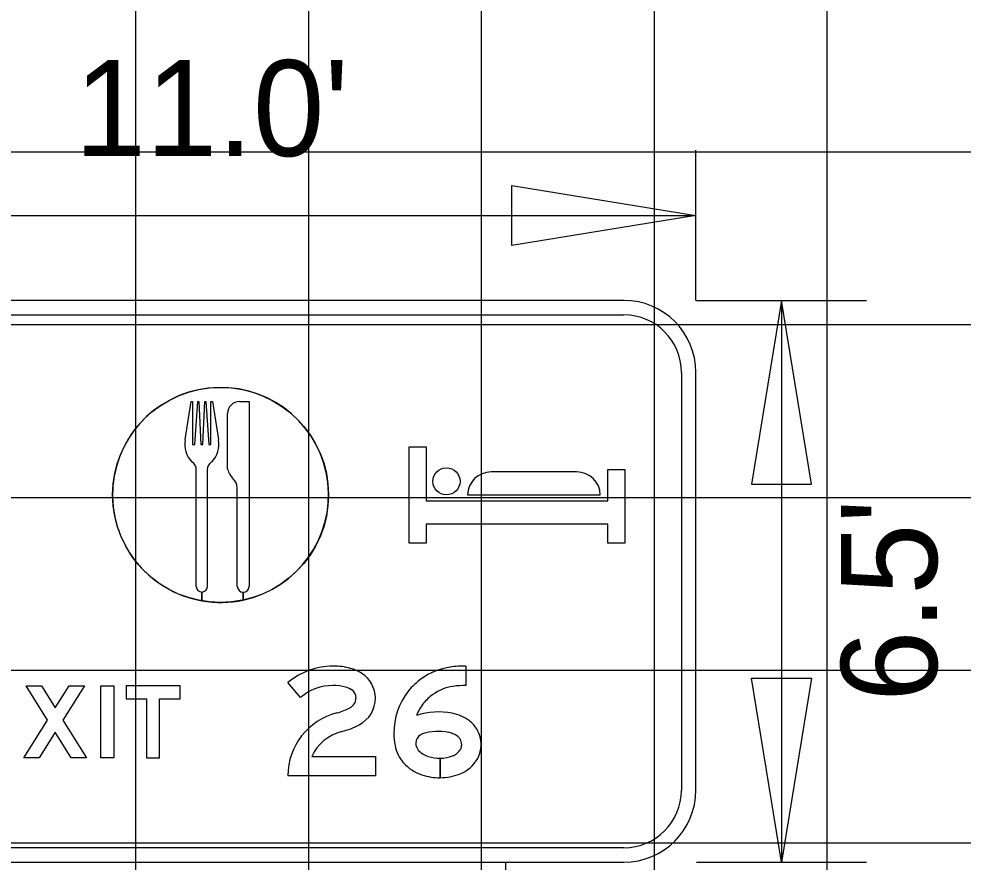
# Model space of a CAD drawing. Extents: x 1797809 to 2198143, y 249608 to 1237864.
# Drawn here: x 2194983.51 to 2194994.43, y 1237299.88 to 1237309.65 of the extents above; entities that cross this region are included whole.
import ezdxf

# ---------------------------------------------------------------- set-up
doc = ezdxf.new("R2010")
doc.units = 0
for name, color, linetype in [('GSBWFILL', 7, 'Continuous'), ('GSCOLORFILL', 7, 'Continuous'), ('GSDIMS', 7, 'Continuous'), ('GSOUTLINE', 7, 'Continuous'), ('GSSHT', 7, 'Continuous'), ('Level 55', 7, 'Continuous')]:
    doc.layers.add(name, color=color, linetype=linetype)

msp = doc.modelspace()

# ---------------------------------------------------------------- linework, layer by layer
at = {"layer": 'GSBWFILL'}
for points in [[(2194985.429, 1237304.774), (2194985.5, 1237305.214), (2194985.516, 1237305.214), (2194985.516, 1237304.716), (2194985.543, 1237304.716), (2194985.577, 1237305.214), (2194985.588, 1237305.214), (2194985.61, 1237304.716), (2194985.635, 1237304.716), (2194985.657, 1237305.214), (2194985.668, 1237305.214), (2194985.703, 1237304.716), (2194985.729, 1237304.716), (2194985.729, 1237305.214), (2194985.745, 1237305.214)], [(2194985.745, 1237305.214), (2194985.816, 1237304.774)], [(2194986.059, 1237305.214), (2194986.172, 1237305.214), (2194986.172, 1237303.078)], [(2194985.921, 1237304.433), (2194985.921, 1237305.077)], [(2194985.559, 1237303.073), (2194985.559, 1237304.424)], [(2194985.686, 1237304.424), (2194985.686, 1237303.073)], [(2194989.96, 1237304.401), (2194988.972, 1237304.401)], [(2194986.033, 1237303.078), (2194986.033, 1237304.216)], [(2194988.698, 1237304.134), (2194990.234, 1237304.134)], [(2194985.622, 1237302.909), (2194985.622, 1237303.009)], [(2194985.623, 1237303.009), (2194985.623, 1237302.909)], [(2194986.103, 1237302.917), (2194986.103, 1237303.009)], [(2194986.103, 1237303.009), (2194986.103, 1237302.917)], [(2194988.679, 1237302.153), (2194988.679, 1237301.928)], [(2194986.765, 1237301.79), (2194986.62, 1237301.962)], [(2194986.894, 1237301.107), (2194987.631, 1237301.107), (2194987.631, 1237300.882), (2194986.62, 1237300.882)], [(2194988.382, 1237301.085), (2194988.382, 1237300.861)], [(2194988.382, 1237300.861), (2194988.382, 1237301.085)]]:
    msp.add_lwpolyline(points, dxfattribs=at)
for points in [[(2194990.32, 1237303.794), (2194988.22, 1237303.794), (2194988.22, 1237303.576), (2194988.021, 1237303.576), (2194988.021, 1237304.692), (2194988.22, 1237304.692), (2194988.22, 1237304.065), (2194990.32, 1237304.065), (2194990.32, 1237304.427), (2194990.519, 1237304.427), (2194990.519, 1237303.576), (2194990.32, 1237303.576)], [(2194984.112, 1237301.09), (2194983.926, 1237301.386), (2194983.741, 1237301.09), (2194983.564, 1237301.09), (2194983.838, 1237301.527), (2194983.589, 1237301.923), (2194983.766, 1237301.923), (2194983.926, 1237301.668), (2194984.087, 1237301.923), (2194984.264, 1237301.923), (2194984.015, 1237301.527), (2194984.288, 1237301.09)], [(2194984.455, 1237301.09), (2194984.455, 1237301.923), (2194984.605, 1237301.923), (2194984.605, 1237301.09)], [(2194984.746, 1237301.773), (2194984.984, 1237301.773), (2194984.984, 1237301.09), (2194985.133, 1237301.09), (2194985.133, 1237301.773), (2194985.371, 1237301.773), (2194985.371, 1237301.923), (2194984.746, 1237301.923)]]:
    msp.add_lwpolyline(points, close=True, dxfattribs=at)
for centre, major_axis, ratio, start_param, end_param in [((2194985.84, 1237304.134), (1.249, 0), 0.996678, 4.924399, 10.820496), ((2194986.059, 1237305.077), (0.138, 0), 0.996678, 1.570796, 3.141593), ((2194985.711, 1237304.72), (0.287, 0), 0.996678, 2.953442, 3.930823), ((2194985.535, 1237304.72), (0.287, 0), 0.996678, 5.493955, 6.471336), ((2194985.454, 1237304.428), (0.105, 0), 0.996678, 6.242039, 7.30582), ((2194985.791, 1237304.428), (0.105, 0), 0.996678, 2.118958, 3.182739), ((2194986.15, 1237304.49), (0.236, 0), 0.996678, 3.390184, 3.947625), ((2194988.972, 1237304.13), (0.274, 0), 0.989161, 1.570796, 3.125706), ((2194989.96, 1237304.13), (0.274, 0), 0.989161, 0.015887, 1.570796), ((2194985.891, 1237304.216), (0.142, 0), 0.996678, 6.282388, 7.120714), ((2194985.623, 1237303.073), (0.0637, 0), 0.996678, 3.141593, 4.710428), ((2194985.623, 1237303.073), (0.0637, 0), 0.996678, 4.712389, 6.283185), ((2194986.103, 1237303.078), (0.0696, 0), 0.996678, 3.141593, 4.710594), ((2194986.103, 1237303.078), (0.0696, 0), 0.996678, 4.712389, 6.283185), ((2194985.84, 1237304.134), (1.249, 0), 0.996678, 4.537413, 4.924296), ((2194987.141, 1237301.347), (0, 0.806), 0.999999, 0, 0.70376), ((2194987.141, 1237301.364), (0, 0.789), 0.999999, 6.02311, 6.283185), ((2194987.226, 1237301.684), (0, 0.458), 0.999999, 5.706931, 6.02311), ((2194988.596, 1237301.418), (0, 0.729), 0.999999, 0.134155, 0.638471), ((2194988.679, 1237300.802), (0, 1.351), 0.999999, 6.283185, 6.41734), ((2194987.29, 1237301.782), (0, 0.341), 0.999999, 4.712389, 5.706931), ((2194988.693, 1237301.288), (0, 0.892), 0.999999, 0.638464, 0.866813), ((2194987.141, 1237301.347), (0, 0.581), 0.999999, 0, 0.70376), ((2194987.141, 1237301.364), (0, 0.565), 0.999999, 6.02311, 6.283185), ((2194987.226, 1237301.684), (0, 0.233), 0.999999, 5.706931, 6.02311), ((2194987.29, 1237301.782), (0, 0.117), 0.999999, 4.712389, 5.706931), ((2194988.64, 1237301.373), (0, 0.796), 0.999999, 0.905406, 1.570796), ((2194988.596, 1237301.418), (0, 0.504), 0.999999, 0.134155, 0.638471), ((2194988.679, 1237300.802), (0, 1.126), 0.999999, 0, 0.134155), ((2194987.282, 1237301.782), (0, 0.124), 0.999999, 3.626327, 4.712389), ((2194987.282, 1237301.782), (0, 0.349), 0.999999, 3.626327, 4.712389), ((2194988.693, 1237301.288), (0, 0.667), 0.999999, 0.638461, 0.860244), ((2194987.012, 1237302.294), (0, 0.704), 0.999999, 3.392123, 3.626327), ((2194988.64, 1237301.373), (0, 0.572), 0.999999, 0.912917, 1.195206), ((2194987.373, 1237300.882), (0, 0.754), 0.999999, 0.25053, 1.570796), ((2194988.361, 1237300.794), (0, 0.828), 0.999999, 6.090019, 6.593179), ((2194988.426, 1237301.13), (0, 0.486), 0.999999, 5.634496, 6.090017), ((2194987.012, 1237302.294), (0, 0.928), 0.999999, 3.392123, 3.626327), ((2194988.518, 1237301.251), (0, 0.335), 0.999999, 5.237857, 5.634492), ((2194987.373, 1237300.882), (0, 0.529), 0.999999, 0.25053, 1.132058), ((2194988.509, 1237301.373), (0, 0.665), 0.999999, 1.570796, 1.784619), ((2194988.218, 1237301.257), (0, 0.119), 0.999999, 0.35159, 2.216564), ((2194988.361, 1237300.794), (0, 0.603), 0.999999, 6.090019, 6.593179), ((2194988.426, 1237301.13), (0, 0.262), 0.999999, 5.6345, 6.090015), ((2194988.518, 1237301.251), (0, 0.11), 0.999999, 5.237857, 5.634492), ((2194988.503, 1237301.242), (0, 0.352), 0.999999, 4.712389, 5.237857), ((2194988.253, 1237301.303), (0, 0.401), 0.999999, 1.748918, 2.304124), ((2194988.503, 1237301.242), (0, 0.127), 0.999999, 4.712389, 5.237857), ((2194988.515, 1237301.242), (0, 0.115), 0.999999, 4.261086, 4.712389), ((2194988.515, 1237301.242), (0, 0.339), 0.999999, 4.229443, 4.712389), ((2194988.326, 1237301.368), (0, 0.274), 0.999999, 2.304124, 2.823757), ((2194988.382, 1237301.539), (0, 0.454), 0.999999, 2.823757, 3.141593), ((2194988.382, 1237301.475), (0, 0.389), 0.999999, 3.141673, 3.514879), ((2194988.454, 1237301.291), (0, 0.192), 0.999999, 3.51487, 4.172439), ((2194988.326, 1237301.368), (0, 0.499), 0.999999, 2.304124, 2.823757), ((2194988.454, 1237301.291), (0, 0.417), 0.999999, 3.514875, 4.194509), ((2194988.382, 1237301.539), (0, 0.679), 0.999999, 2.823757, 3.141593), ((2194988.382, 1237301.475), (0, 0.614), 0.999999, 3.141643, 3.514879)]:
    msp.add_ellipse(centre, major_axis=major_axis, ratio=ratio, start_param=start_param, end_param=end_param, dxfattribs=at)
msp.add_ellipse((2194988.453, 1237304.291), major_axis=(0.158, 0), ratio=0.989161, dxfattribs=at)
at = {"layer": 'GSCOLORFILL'}
for p, q in [((2194990.507, 1237306.385), (2194981.175, 1237306.385)), ((2194981.175, 1237306.219), (2194990.507, 1237306.219)), ((2194991.173, 1237305.553), (2194991.173, 1237300.716)), ((2194991.34, 1237300.716), (2194991.34, 1237305.553)), ((2194990.507, 1237300.05), (2194981.177, 1237300.05)), ((2194981.177, 1237299.883), (2194990.507, 1237299.883))]:
    msp.add_line(p, q, dxfattribs=at)
for points in [[(2194985.429, 1237304.774), (2194985.5, 1237305.214), (2194985.516, 1237305.214), (2194985.516, 1237304.716), (2194985.543, 1237304.716), (2194985.577, 1237305.214), (2194985.588, 1237305.214), (2194985.61, 1237304.716), (2194985.635, 1237304.716), (2194985.657, 1237305.214), (2194985.668, 1237305.214), (2194985.703, 1237304.716), (2194985.729, 1237304.716), (2194985.729, 1237305.214), (2194985.745, 1237305.214)], [(2194985.745, 1237305.214), (2194985.816, 1237304.774)], [(2194986.059, 1237305.214), (2194986.172, 1237305.214), (2194986.172, 1237303.078)], [(2194985.921, 1237304.433), (2194985.921, 1237305.077)], [(2194985.559, 1237303.073), (2194985.559, 1237304.424)], [(2194985.686, 1237304.424), (2194985.686, 1237303.073)], [(2194989.96, 1237304.401), (2194988.972, 1237304.401)], [(2194986.033, 1237303.078), (2194986.033, 1237304.216)], [(2194988.698, 1237304.134), (2194990.234, 1237304.134)], [(2194985.622, 1237302.909), (2194985.622, 1237303.009)], [(2194985.623, 1237303.009), (2194985.623, 1237302.909)], [(2194986.103, 1237302.917), (2194986.103, 1237303.009)], [(2194986.103, 1237303.009), (2194986.103, 1237302.917)], [(2194988.679, 1237302.153), (2194988.679, 1237301.928)], [(2194986.765, 1237301.79), (2194986.62, 1237301.962)], [(2194986.894, 1237301.107), (2194987.631, 1237301.107), (2194987.631, 1237300.882), (2194986.62, 1237300.882)], [(2194988.382, 1237301.085), (2194988.382, 1237300.861)], [(2194988.382, 1237300.861), (2194988.382, 1237301.085)]]:
    msp.add_lwpolyline(points, dxfattribs=at)
for points in [[(2194990.32, 1237303.794), (2194988.22, 1237303.794), (2194988.22, 1237303.576), (2194988.021, 1237303.576), (2194988.021, 1237304.692), (2194988.22, 1237304.692), (2194988.22, 1237304.065), (2194990.32, 1237304.065), (2194990.32, 1237304.427), (2194990.519, 1237304.427), (2194990.519, 1237303.576), (2194990.32, 1237303.576)], [(2194984.112, 1237301.09), (2194983.926, 1237301.386), (2194983.741, 1237301.09), (2194983.564, 1237301.09), (2194983.838, 1237301.527), (2194983.589, 1237301.923), (2194983.766, 1237301.923), (2194983.926, 1237301.668), (2194984.087, 1237301.923), (2194984.264, 1237301.923), (2194984.015, 1237301.527), (2194984.288, 1237301.09)], [(2194984.455, 1237301.09), (2194984.455, 1237301.923), (2194984.605, 1237301.923), (2194984.605, 1237301.09)], [(2194984.746, 1237301.773), (2194984.984, 1237301.773), (2194984.984, 1237301.09), (2194985.133, 1237301.09), (2194985.133, 1237301.773), (2194985.371, 1237301.773), (2194985.371, 1237301.923), (2194984.746, 1237301.923)]]:
    msp.add_lwpolyline(points, close=True, dxfattribs=at)
for centre, radius, start, end in [((2194990.507, 1237305.553), 0.833, 0, 90), ((2194990.507, 1237305.553), 0.666, 0, 90), ((2194990.507, 1237300.716), 0.833, 270, 0), ((2194990.507, 1237300.716), 0.666, 270, 0)]:
    msp.add_arc(centre, radius, start, end, dxfattribs=at)
for centre, major_axis, ratio, start_param, end_param in [((2194985.84, 1237304.134), (1.249, 0), 0.996678, 4.924399, 10.820496), ((2194986.059, 1237305.077), (0.138, 0), 0.996678, 1.570796, 3.141593), ((2194985.711, 1237304.72), (0.287, 0), 0.996678, 2.953442, 3.930823), ((2194985.535, 1237304.72), (0.287, 0), 0.996678, 5.493955, 6.471336), ((2194985.454, 1237304.428), (0.105, 0), 0.996678, 6.242039, 7.30582), ((2194985.791, 1237304.428), (0.105, 0), 0.996678, 2.118958, 3.182739), ((2194986.15, 1237304.49), (0.236, 0), 0.996678, 3.390184, 3.947625), ((2194988.972, 1237304.13), (0.274, 0), 0.989161, 1.570796, 3.125706), ((2194989.96, 1237304.13), (0.274, 0), 0.989161, 0.015887, 1.570796), ((2194985.891, 1237304.216), (0.142, 0), 0.996678, 6.282388, 7.120714), ((2194985.623, 1237303.073), (0.0637, 0), 0.996678, 3.141593, 4.710428), ((2194985.623, 1237303.073), (0.0637, 0), 0.996678, 4.712389, 6.283185), ((2194986.103, 1237303.078), (0.0696, 0), 0.996678, 3.141593, 4.710594), ((2194986.103, 1237303.078), (0.0696, 0), 0.996678, 4.712389, 6.283185), ((2194985.84, 1237304.134), (1.249, 0), 0.996678, 4.537413, 4.924296), ((2194987.141, 1237301.347), (0, 0.806), 0.999999, 0, 0.70376), ((2194987.141, 1237301.364), (0, 0.789), 0.999999, 6.02311, 6.283185), ((2194987.226, 1237301.684), (0, 0.458), 0.999999, 5.706931, 6.02311), ((2194988.596, 1237301.418), (0, 0.729), 0.999999, 0.134155, 0.638471), ((2194988.679, 1237300.802), (0, 1.351), 0.999999, 6.283185, 6.41734), ((2194987.29, 1237301.782), (0, 0.341), 0.999999, 4.712389, 5.706931), ((2194988.693, 1237301.288), (0, 0.892), 0.999999, 0.638464, 0.866813), ((2194987.141, 1237301.347), (0, 0.581), 0.999999, 0, 0.70376), ((2194987.141, 1237301.364), (0, 0.565), 0.999999, 6.02311, 6.283185), ((2194987.226, 1237301.684), (0, 0.233), 0.999999, 5.706931, 6.02311), ((2194987.29, 1237301.782), (0, 0.117), 0.999999, 4.712389, 5.706931), ((2194988.64, 1237301.373), (0, 0.796), 0.999999, 0.905406, 1.570796), ((2194988.596, 1237301.418), (0, 0.504), 0.999999, 0.134155, 0.638471), ((2194988.679, 1237300.802), (0, 1.126), 0.999999, 0, 0.134155), ((2194987.282, 1237301.782), (0, 0.124), 0.999999, 3.626327, 4.712389), ((2194987.282, 1237301.782), (0, 0.349), 0.999999, 3.626327, 4.712389), ((2194988.693, 1237301.288), (0, 0.667), 0.999999, 0.638461, 0.860244), ((2194987.012, 1237302.294), (0, 0.704), 0.999999, 3.392123, 3.626327), ((2194988.64, 1237301.373), (0, 0.572), 0.999999, 0.912917, 1.195206), ((2194987.373, 1237300.882), (0, 0.754), 0.999999, 0.25053, 1.570796), ((2194988.361, 1237300.794), (0, 0.828), 0.999999, 6.090019, 6.593179), ((2194988.426, 1237301.13), (0, 0.486), 0.999999, 5.634496, 6.090017), ((2194987.012, 1237302.294), (0, 0.928), 0.999999, 3.392123, 3.626327), ((2194988.518, 1237301.251), (0, 0.335), 0.999999, 5.237857, 5.634492), ((2194987.373, 1237300.882), (0, 0.529), 0.999999, 0.25053, 1.132058), ((2194988.509, 1237301.373), (0, 0.665), 0.999999, 1.570796, 1.784619), ((2194988.218, 1237301.257), (0, 0.119), 0.999999, 0.35159, 2.216564), ((2194988.361, 1237300.794), (0, 0.603), 0.999999, 6.090019, 6.593179), ((2194988.426, 1237301.13), (0, 0.262), 0.999999, 5.6345, 6.090015), ((2194988.518, 1237301.251), (0, 0.11), 0.999999, 5.237857, 5.634492), ((2194988.503, 1237301.242), (0, 0.352), 0.999999, 4.712389, 5.237857), ((2194988.253, 1237301.303), (0, 0.401), 0.999999, 1.748918, 2.304124), ((2194988.503, 1237301.242), (0, 0.127), 0.999999, 4.712389, 5.237857), ((2194988.515, 1237301.242), (0, 0.115), 0.999999, 4.261086, 4.712389), ((2194988.515, 1237301.242), (0, 0.339), 0.999999, 4.229443, 4.712389), ((2194988.326, 1237301.368), (0, 0.274), 0.999999, 2.304124, 2.823757), ((2194988.382, 1237301.539), (0, 0.454), 0.999999, 2.823757, 3.141593), ((2194988.382, 1237301.475), (0, 0.389), 0.999999, 3.141673, 3.514879), ((2194988.454, 1237301.291), (0, 0.192), 0.999999, 3.51487, 4.172439), ((2194988.326, 1237301.368), (0, 0.499), 0.999999, 2.304124, 2.823757), ((2194988.454, 1237301.291), (0, 0.417), 0.999999, 3.514875, 4.194509), ((2194988.382, 1237301.539), (0, 0.679), 0.999999, 2.823757, 3.141593), ((2194988.382, 1237301.475), (0, 0.614), 0.999999, 3.141643, 3.514879)]:
    msp.add_ellipse(centre, major_axis=major_axis, ratio=ratio, start_param=start_param, end_param=end_param, dxfattribs=at)
msp.add_ellipse((2194988.453, 1237304.291), major_axis=(0.158, 0), ratio=0.989161, dxfattribs=at)
at = {"layer": 'GSDIMS'}
for p, q in [((2194991.34, 1237306.385), (2194991.34, 1237308.127)), ((2194980.343, 1237307.369), (2194991.34, 1237307.369)), ((2194991.348, 1237306.385), (2194993.316, 1237306.385)), ((2194992.332, 1237306.385), (2194992.332, 1237299.883)), ((2194989.14, 1237286.258), (2194989.14, 1237299.883)), ((2194991.348, 1237299.883), (2194993.316, 1237299.883))]:
    msp.add_line(p, q, dxfattribs=at)
for points in [[(2194991.34, 1237307.369), (2194989.211, 1237307.022), (2194989.211, 1237307.716)], [(2194992.332, 1237306.385), (2194991.985, 1237304.257), (2194992.679, 1237304.257)], [(2194992.332, 1237299.883), (2194991.985, 1237302.012), (2194992.679, 1237302.012)]]:
    msp.add_lwpolyline(points, close=True, dxfattribs=at)
at = {"layer": 'GSOUTLINE'}
for points in [[(2194985.429, 1237304.774), (2194985.5, 1237305.214), (2194985.516, 1237305.214), (2194985.516, 1237304.716), (2194985.543, 1237304.716), (2194985.577, 1237305.214), (2194985.588, 1237305.214)], [(2194985.588, 1237305.214), (2194985.61, 1237304.716), (2194985.635, 1237304.716), (2194985.657, 1237305.214), (2194985.668, 1237305.214), (2194985.703, 1237304.716), (2194985.729, 1237304.716), (2194985.729, 1237305.214), (2194985.745, 1237305.214), (2194985.816, 1237304.774)], [(2194986.059, 1237305.214), (2194986.172, 1237305.214), (2194986.172, 1237303.078)], [(2194985.921, 1237304.433), (2194985.921, 1237305.077)], [(2194985.559, 1237303.073), (2194985.559, 1237304.424)], [(2194985.686, 1237304.424), (2194985.686, 1237303.073)], [(2194989.96, 1237304.401), (2194988.972, 1237304.401)], [(2194986.033, 1237303.078), (2194986.033, 1237304.216)], [(2194988.698, 1237304.134), (2194990.234, 1237304.134)], [(2194988.679, 1237302.153), (2194988.679, 1237301.928)], [(2194986.765, 1237301.79), (2194986.62, 1237301.962)], [(2194986.894, 1237301.107), (2194987.631, 1237301.107), (2194987.631, 1237300.882), (2194986.62, 1237300.882)]]:
    msp.add_lwpolyline(points, dxfattribs=at)
for points in [[(2194990.32, 1237303.794), (2194988.22, 1237303.794), (2194988.22, 1237303.576), (2194988.021, 1237303.576), (2194988.021, 1237304.692), (2194988.22, 1237304.692), (2194988.22, 1237304.065), (2194990.32, 1237304.065), (2194990.32, 1237304.427), (2194990.519, 1237304.427), (2194990.519, 1237303.576), (2194990.32, 1237303.576)], [(2194984.112, 1237301.09), (2194983.926, 1237301.386), (2194983.741, 1237301.09), (2194983.564, 1237301.09), (2194983.838, 1237301.527), (2194983.589, 1237301.923), (2194983.766, 1237301.923), (2194983.926, 1237301.668), (2194984.087, 1237301.923), (2194984.264, 1237301.923), (2194984.015, 1237301.527), (2194984.288, 1237301.09)], [(2194984.455, 1237301.09), (2194984.455, 1237301.923), (2194984.605, 1237301.923), (2194984.605, 1237301.09)], [(2194984.746, 1237301.773), (2194984.984, 1237301.773), (2194984.984, 1237301.09), (2194985.133, 1237301.09), (2194985.133, 1237301.773), (2194985.371, 1237301.773), (2194985.371, 1237301.923), (2194984.746, 1237301.923)]]:
    msp.add_lwpolyline(points, close=True, dxfattribs=at)
for centre, major_axis, ratio in [((2194985.84, 1237304.134), (1.249, 0), 0.996678), ((2194988.453, 1237304.291), (0.158, 0), 0.989161)]:
    msp.add_ellipse(centre, major_axis=major_axis, ratio=ratio, dxfattribs=at)
for centre, major_axis, ratio, start_param, end_param in [((2194986.059, 1237305.077), (0.138, 0), 0.996678, 1.570796, 3.141593), ((2194985.711, 1237304.72), (0.287, 0), 0.996678, 2.953442, 3.930823), ((2194985.535, 1237304.72), (0.287, 0), 0.996678, 5.493955, 6.471336), ((2194985.454, 1237304.428), (0.105, 0), 0.996678, 6.242039, 7.30582), ((2194985.791, 1237304.428), (0.105, 0), 0.996678, 2.118958, 3.182739), ((2194986.15, 1237304.49), (0.236, 0), 0.996678, 3.390184, 3.947625), ((2194988.972, 1237304.13), (0.274, 0), 0.989161, 1.570796, 3.125706), ((2194989.96, 1237304.13), (0.274, 0), 0.989161, 0.015887, 1.570796), ((2194985.891, 1237304.216), (0.142, 0), 0.996678, 6.282388, 7.120714), ((2194985.623, 1237303.073), (0.0637, 0), 0.996678, 3.141593, 6.283185), ((2194986.103, 1237303.078), (0.0696, 0), 0.996678, 3.141593, 6.283185), ((2194987.141, 1237301.347), (0, 0.806), 0.999999, 0, 0.70376), ((2194987.141, 1237301.364), (0, 0.789), 0.999999, 6.02311, 6.283185), ((2194987.226, 1237301.684), (0, 0.458), 0.999999, 5.706931, 6.02311), ((2194988.596, 1237301.418), (0, 0.729), 0.999999, 0.134155, 0.638471), ((2194988.679, 1237300.802), (0, 1.351), 0.999999, 6.283185, 6.41734), ((2194987.29, 1237301.782), (0, 0.341), 0.999999, 4.712389, 5.706931), ((2194988.693, 1237301.288), (0, 0.892), 0.999999, 0.638464, 0.866813), ((2194987.141, 1237301.347), (0, 0.581), 0.999999, 0, 0.70376), ((2194987.141, 1237301.364), (0, 0.565), 0.999999, 6.02311, 6.283185), ((2194987.226, 1237301.684), (0, 0.233), 0.999999, 5.706931, 6.02311), ((2194987.29, 1237301.782), (0, 0.117), 0.999999, 4.712389, 5.706931), ((2194988.64, 1237301.373), (0, 0.796), 0.999999, 0.905406, 1.570796), ((2194988.596, 1237301.418), (0, 0.504), 0.999999, 0.134155, 0.638471), ((2194988.679, 1237300.802), (0, 1.126), 0.999999, 0, 0.134155), ((2194987.282, 1237301.782), (0, 0.124), 0.999999, 3.626327, 4.712389), ((2194987.282, 1237301.782), (0, 0.349), 0.999999, 3.626327, 4.712389), ((2194988.693, 1237301.288), (0, 0.667), 0.999999, 0.638461, 0.860244), ((2194987.012, 1237302.294), (0, 0.704), 0.999999, 3.392123, 3.626327), ((2194988.64, 1237301.373), (0, 0.572), 0.999999, 0.912917, 1.195206), ((2194987.373, 1237300.882), (0, 0.754), 0.999999, 0.25053, 1.570796), ((2194988.361, 1237300.794), (0, 0.828), 0.999999, 6.090019, 6.593179), ((2194988.426, 1237301.13), (0, 0.486), 0.999999, 5.634496, 6.090017), ((2194987.012, 1237302.294), (0, 0.928), 0.999999, 3.392123, 3.626327), ((2194988.518, 1237301.251), (0, 0.335), 0.999999, 5.237857, 5.634492), ((2194987.373, 1237300.882), (0, 0.529), 0.999999, 0.25053, 1.132058), ((2194988.509, 1237301.373), (0, 0.665), 0.999999, 1.570796, 1.784619), ((2194988.218, 1237301.257), (0, 0.119), 0.999999, 0.35159, 2.216564), ((2194988.361, 1237300.794), (0, 0.603), 0.999999, 6.090019, 6.593179), ((2194988.426, 1237301.13), (0, 0.262), 0.999999, 5.6345, 6.090015), ((2194988.518, 1237301.251), (0, 0.11), 0.999999, 5.237857, 5.634492), ((2194988.503, 1237301.242), (0, 0.352), 0.999999, 4.712389, 5.237857), ((2194988.253, 1237301.303), (0, 0.401), 0.999999, 1.748918, 2.304124), ((2194988.503, 1237301.242), (0, 0.127), 0.999999, 4.712389, 5.237857), ((2194988.515, 1237301.242), (0, 0.115), 0.999999, 4.261086, 4.712389), ((2194988.515, 1237301.242), (0, 0.339), 0.999999, 4.229443, 4.712389), ((2194988.326, 1237301.368), (0, 0.274), 0.999999, 2.304124, 2.823757), ((2194988.382, 1237301.539), (0, 0.454), 0.999999, 2.823757, 3.141593), ((2194988.382, 1237301.475), (0, 0.389), 0.999999, 3.141593, 3.514879), ((2194988.454, 1237301.291), (0, 0.192), 0.999999, 3.51487, 4.172439), ((2194988.326, 1237301.368), (0, 0.499), 0.999999, 2.304124, 2.823757), ((2194988.454, 1237301.291), (0, 0.417), 0.999999, 3.514875, 4.194509), ((2194988.382, 1237301.539), (0, 0.679), 0.999999, 2.823757, 3.141593), ((2194988.382, 1237301.475), (0, 0.614), 0.999999, 3.141593, 3.514879)]:
    msp.add_ellipse(centre, major_axis=major_axis, ratio=ratio, start_param=start_param, end_param=end_param, dxfattribs=at)
at = {"layer": 'GSSHT'}
for p, q in [((2194984.86, 1237258.106), (2194984.86, 1237318.106)), ((2194986.86, 1237258.106), (2194986.86, 1237318.106)), ((2194988.86, 1237258.106), (2194988.86, 1237318.106)), ((2194990.86, 1237258.106), (2194990.86, 1237318.106)), ((2194992.86, 1237258.106), (2194992.86, 1237318.106)), ((2194892.86, 1237308.106), (2195022.86, 1237308.106)), ((2194892.86, 1237306.106), (2195022.86, 1237306.106)), ((2194892.86, 1237304.106), (2195022.86, 1237304.106)), ((2194892.86, 1237302.106), (2195022.86, 1237302.106)), ((2194892.86, 1237300.106), (2195022.86, 1237300.106))]:
    msp.add_line(p, q, dxfattribs=at)

# ---------------------------------------------------------------- texts
at = {"layer": 'Level 55'}
msp.add_text("11.0'", height=1.1105, dxfattribs=at).set_placement((2194984.151, 1237308.057))
msp.add_text("6.5'", height=1.1105, rotation=90, dxfattribs=at).set_placement((2194994.13, 1237301.739))

doc.saveas('drawing.dxf')
